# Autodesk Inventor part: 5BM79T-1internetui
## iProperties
Created: 2010-11
Part Number: 5BM79T-1internetui
Document SubType Name: Modeling
Designer: Darius
Author: Darius
Translation Standard: STEP AP203
File Name: 5BM79T-1.STEP
Preprocessor: SolidWorks 2003240
Postprocessor: Build: 272, Release: 10 SP3a - Date: Thu 12/15/2005
Sent Units: MILLIMETERS
Uncertainty: 1e-05
